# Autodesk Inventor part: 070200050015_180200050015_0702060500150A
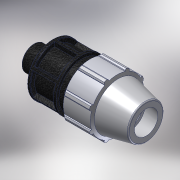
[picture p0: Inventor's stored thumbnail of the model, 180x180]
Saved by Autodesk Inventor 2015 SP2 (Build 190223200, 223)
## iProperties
Created: 2017-02
Part Number: 070200050015_180200050015_0702060500150A
Material: PVC-Piping
Description: PLASSON MALE ADAPTOR 50-1.1/2"
Document SubType Name: Modeling
Designer: KIM
Mass: 92.6774 g
Surface Area: 199.44 cm^2
Volume: 66.1981 cm^3
Density: 1.4 g/cm^3
Appearance: PTFE
Author: KIM
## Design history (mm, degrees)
derived "07020.ipt"
feature "Solid1::07020.ipt"
tag "TaggingFeature1"
body "Solid1"
other parameters: "d4" = 19.42857, "d5" = 34, "d7" = 96, "d8" = 72, "d9" = 19.42857, "d11" = 3.88571, "d12" = 76.8, "d13" = 120 deg, "d14" = 75, "d15" = 8 deg, "d16" = 86.4, "d18" = 2.5, "d19" = 35 deg, "d20" = 17.5 deg, "d21" = 89.28, "d23" = 0, "d25" = 360 deg, "d27" = 1.92, "d34" = 4.8, "d36" = 0, "d42" = 34, "d43" = 2.88, "d46" = 1.5, "d49" = 109, "d51" = 136, "d52" = 22, "d53" = 1, "d55" = 360 deg, "d57" = 47.803, "d58" = 33.4621, "d59" = 27.2, "E_" = 96, "H_" = 136, "l_" = 109, "l_2" = 22, "R_" = 47.803
